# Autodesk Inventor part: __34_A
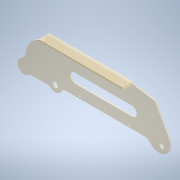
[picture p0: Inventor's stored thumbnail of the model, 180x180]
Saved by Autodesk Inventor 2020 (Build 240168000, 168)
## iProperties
Created: 2017-09
Part Number: __34_A
Material: Bronze, étain doux
Document SubType Name: Modeling
Designer: bruno
Density: 8.874 g/cm^3
Appearance: Huile
Mass: 194.649 g
Surface Area: 235.258 cm^2
Volume: 21.9348 cm^3
Sending System: SolidWorks 2016
Last Author: Prof
Last Saved: 2018-10-03
Author: bruno
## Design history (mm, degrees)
feature "Enlèv. mat.-Extru.1"
sketch "Esquisse1"
  geometry: L1 (202.436, 27.741)-(-106.035, 27.741); L2 (-106.035, 27.741)-(-106.035, -15); L3 (-106.035, -15)-(202.436, -15); L4 (202.436, -15)-(202.436, 27.741); 1 further point
  constraints: 8 end point, 2 parallel, 1 horizontal, 1 perpendicular
extrude "Extrusion1" cut sketch "Esquisse1" distance "d0" = 100; taper "d1" = 0 deg
node "Solide1"
